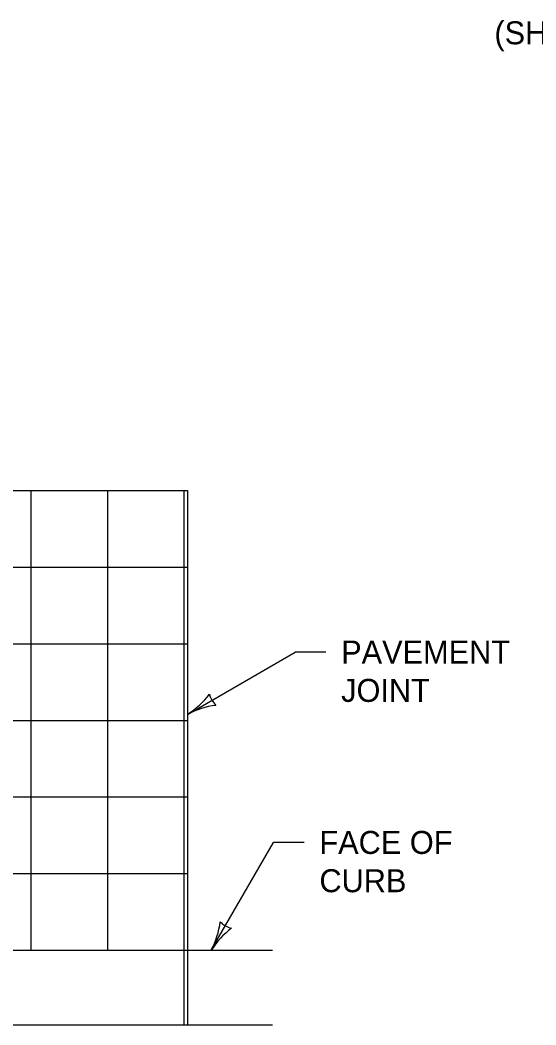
# Model space of a CAD drawing. Extents: x 49991.4 to 50021, y 49987.6 to 50011.4.
# Drawn here: x 50011.432 to 50012.78, y 49993.507 to 49996.13 of the extents above; entities that cross this region are included whole.
import ezdxf

# ---------------------------------------------------------------- set-up
doc = ezdxf.new("R2010")
doc.units = 0
for name, color, linetype in [('Level 1', 7, 'Continuous'), ('Level 2', 7, 'Continuous'), ('Level 3', 7, 'Continuous'), ('Level 4', 7, 'Continuous')]:
    doc.layers.add(name, color=color, linetype=linetype)

msp = doc.modelspace()

# ---------------------------------------------------------------- linework, layer by layer
at = {"layer": 'Level 1'}
for p, q in [((50011.8598, 49994.902), (50011.8598, 49993.507)), ((50011.8692, 49994.902), (50011.8692, 49993.507)), ((50010.3973, 49993.702), (50012.0913, 49993.702)), ((50008.9753, 49993.507), (50012.0913, 49993.507))]:
    msp.add_line(p, q, dxfattribs=at)
at = {"layer": 'Level 2'}
for p, q in [((50011.8692, 49994.3178), (50012.1507, 49994.4803)), ((50012.2307, 49994.4803), (50012.1507, 49994.4803)), ((50011.9313, 49993.702), (50012.0938, 49993.9834)), ((50012.1738, 49993.9834), (50012.0938, 49993.9834))]:
    msp.add_line(p, q, dxfattribs=at)
at = {"layer": 'Level 3'}
for centre, radius, start, end in [((50011.7429, 49994.5136), 0.233, 302.8273, 322.0772), ((50011.9803, 49994.3819), 0.0548, 192.1388, 227.8612), ((50011.9723, 49994.1208), 0.2223, 97.456, 117.6395), ((50011.724, 49993.8084), 0.233, 332.8273, 352.0772), ((50011.9954, 49993.813), 0.0548, 222.1388, 257.8612), ((50012.1191, 49993.583), 0.2223, 127.456, 147.6395)]:
    msp.add_arc(centre, radius, start, end, dxfattribs=at)
at = {"layer": 'Level 4'}
for p, q in [((50008.9753, 49994.902), (50011.8692, 49994.902)), ((50011.4598, 49994.902), (50011.4598, 49993.702)), ((50011.6598, 49994.902), (50011.6598, 49993.702)), ((50008.9753, 49994.702), (50011.8692, 49994.702)), ((50008.9753, 49994.502), (50011.8692, 49994.502)), ((50010.3973, 49994.302), (50011.8692, 49994.302)), ((50010.3973, 49994.102), (50011.8692, 49994.102)), ((50010.3973, 49993.902), (50011.8692, 49993.902))]:
    msp.add_line(p, q, dxfattribs=at)

# ---------------------------------------------------------------- texts
at = {"layer": 'Level 2'}
for s, p in [('(SHOULDER USE ONLY)', (50012.6711, 49996.0671)), ('PAVEMENT', (50012.2707, 49994.4503)), ('JOINT ', (50012.2707, 49994.3503)), ('FACE OF', (50012.2138, 49993.9534)), ('CURB', (50012.2138, 49993.8534))]:
    msp.add_text(s, height=0.06, dxfattribs=at).set_placement(p)

doc.saveas('drawing.dxf')
